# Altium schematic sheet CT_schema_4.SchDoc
size 382 x 218 mm
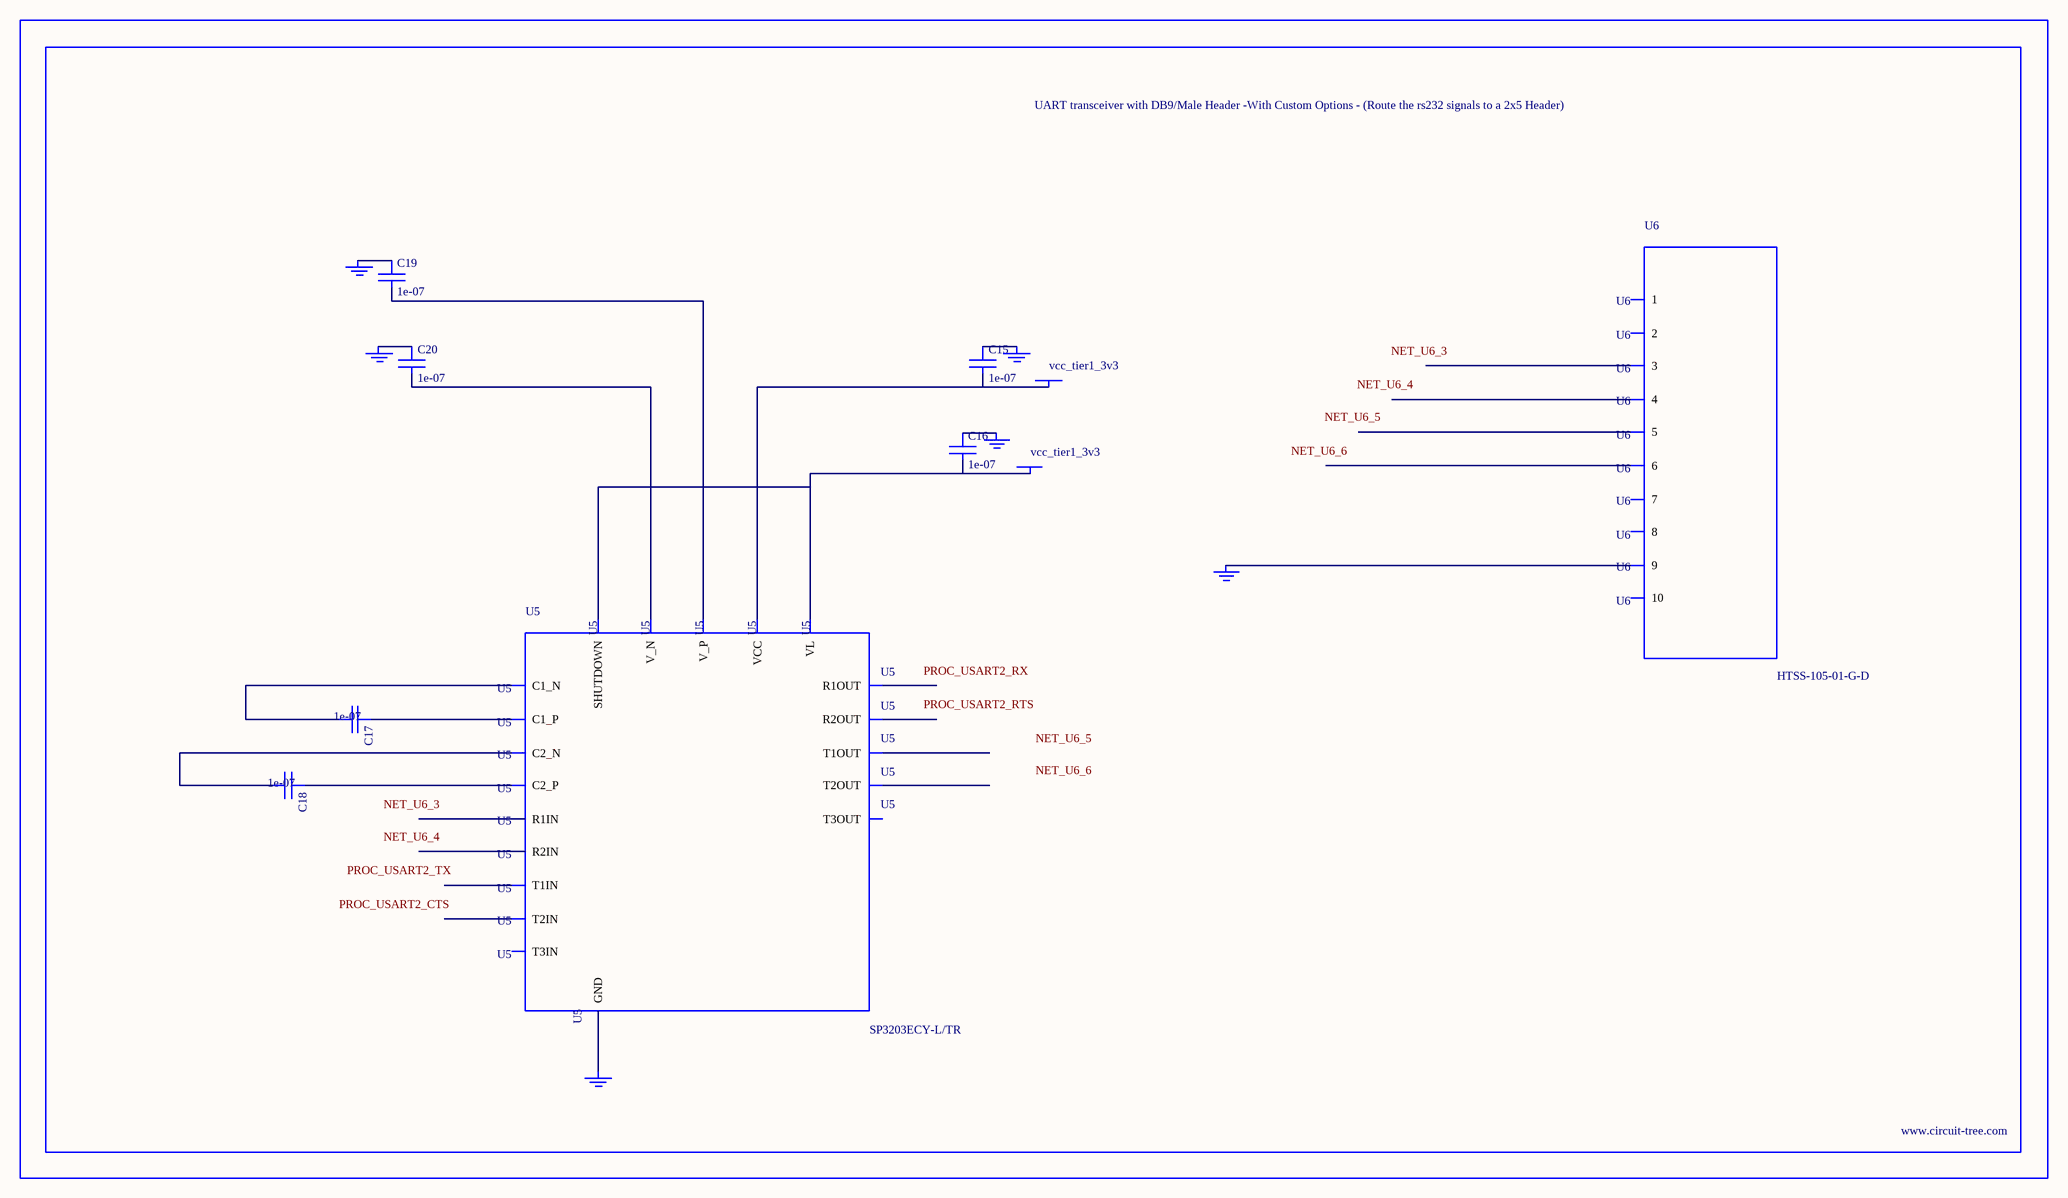
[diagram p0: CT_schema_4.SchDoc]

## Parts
BORDER3  (no value)
C15  1e-07  [C0402]
C16  1e-07  [C0402]
C17  1e-07  [C0402]
C18  1e-07  [C0402]
C19  1e-07  [C0402]
C20  1e-07  [C0402]
GND_INSTANCE_3_0  (no value)
GND_INSTANCE_3_1  (no value)
GND_INSTANCE_3_2  (no value)
GND_INSTANCE_3_3  (no value)
GND_INSTANCE_3_4  (no value)
GND_INSTANCE_3_5  (no value)
POWER_INSTANCE_3_0  vcc_tier1_3v3
POWER_INSTANCE_3_1  vcc_tier1_3v3
U5  SP3203ECY-L/TR  [TSSOP20-I]
U6  HTSS-105-01-G-D  [HTSS-105-01-G-D]

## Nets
NetC15_1: C15.1 GND_INSTANCE_3_3.0(GND)
NetC15_2: C15.2 POWER_INSTANCE_3_1.0(PWR) U5.19(VCC)
NetC16_1: C16.1 GND_INSTANCE_3_2.0(GND)
NetC16_2: C16.2 POWER_INSTANCE_3_0.0(PWR) U5.12(VL) U5.20(SHUTDOWN)
NetC17_1: C17.1 U5.1(C1_P)
NetC17_2: C17.2 U5.3(C1_N)
NetC18_1: C18.1 U5.4(C2_P)
NetC18_2: C18.2 U5.5(C2_N)
NetC19_1: C19.1 GND_INSTANCE_3_0.0(GND)
NetC19_2: C19.2 U5.2(V_P)
NetC20_1: C20.1 GND_INSTANCE_3_1.0(GND)
NetC20_2: C20.2 U5.6(V_N)
NetGND_INSTANCE_3_4_0: GND_INSTANCE_3_4.0(GND) U5.18(GND)
NetGND_INSTANCE_3_5_0: GND_INSTANCE_3_5.0(GND) U6.9

Not connected (* = marked no-connect by the designer): U5 7(T1IN) 8(T2IN) 9(T3IN) 10(R2OUT) 11(R1OUT) 13(R2IN) 14(R1IN) 15(T3OUT) 16(T2OUT) 17(T1OUT); U6 1 2 3 4 5 6 7 8 10

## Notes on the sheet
- Labels drawn without touching a wire or pin: NET_U6_3, NET_U6_4, NET_U6_5, NET_U6_6, PROC_USART2_CTS, PROC_USART2_RTS, PROC_USART2_RX, PROC_USART2_TX

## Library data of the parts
BORDER3 = BORDER_PAGE3
C15-C20 = C0402C104K3RACTU
GND_INSTANCE_3_0-GND_INSTANCE_3_5 = GND
POWER_INSTANCE_3_0 POWER_INSTANCE_3_1 = PWR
